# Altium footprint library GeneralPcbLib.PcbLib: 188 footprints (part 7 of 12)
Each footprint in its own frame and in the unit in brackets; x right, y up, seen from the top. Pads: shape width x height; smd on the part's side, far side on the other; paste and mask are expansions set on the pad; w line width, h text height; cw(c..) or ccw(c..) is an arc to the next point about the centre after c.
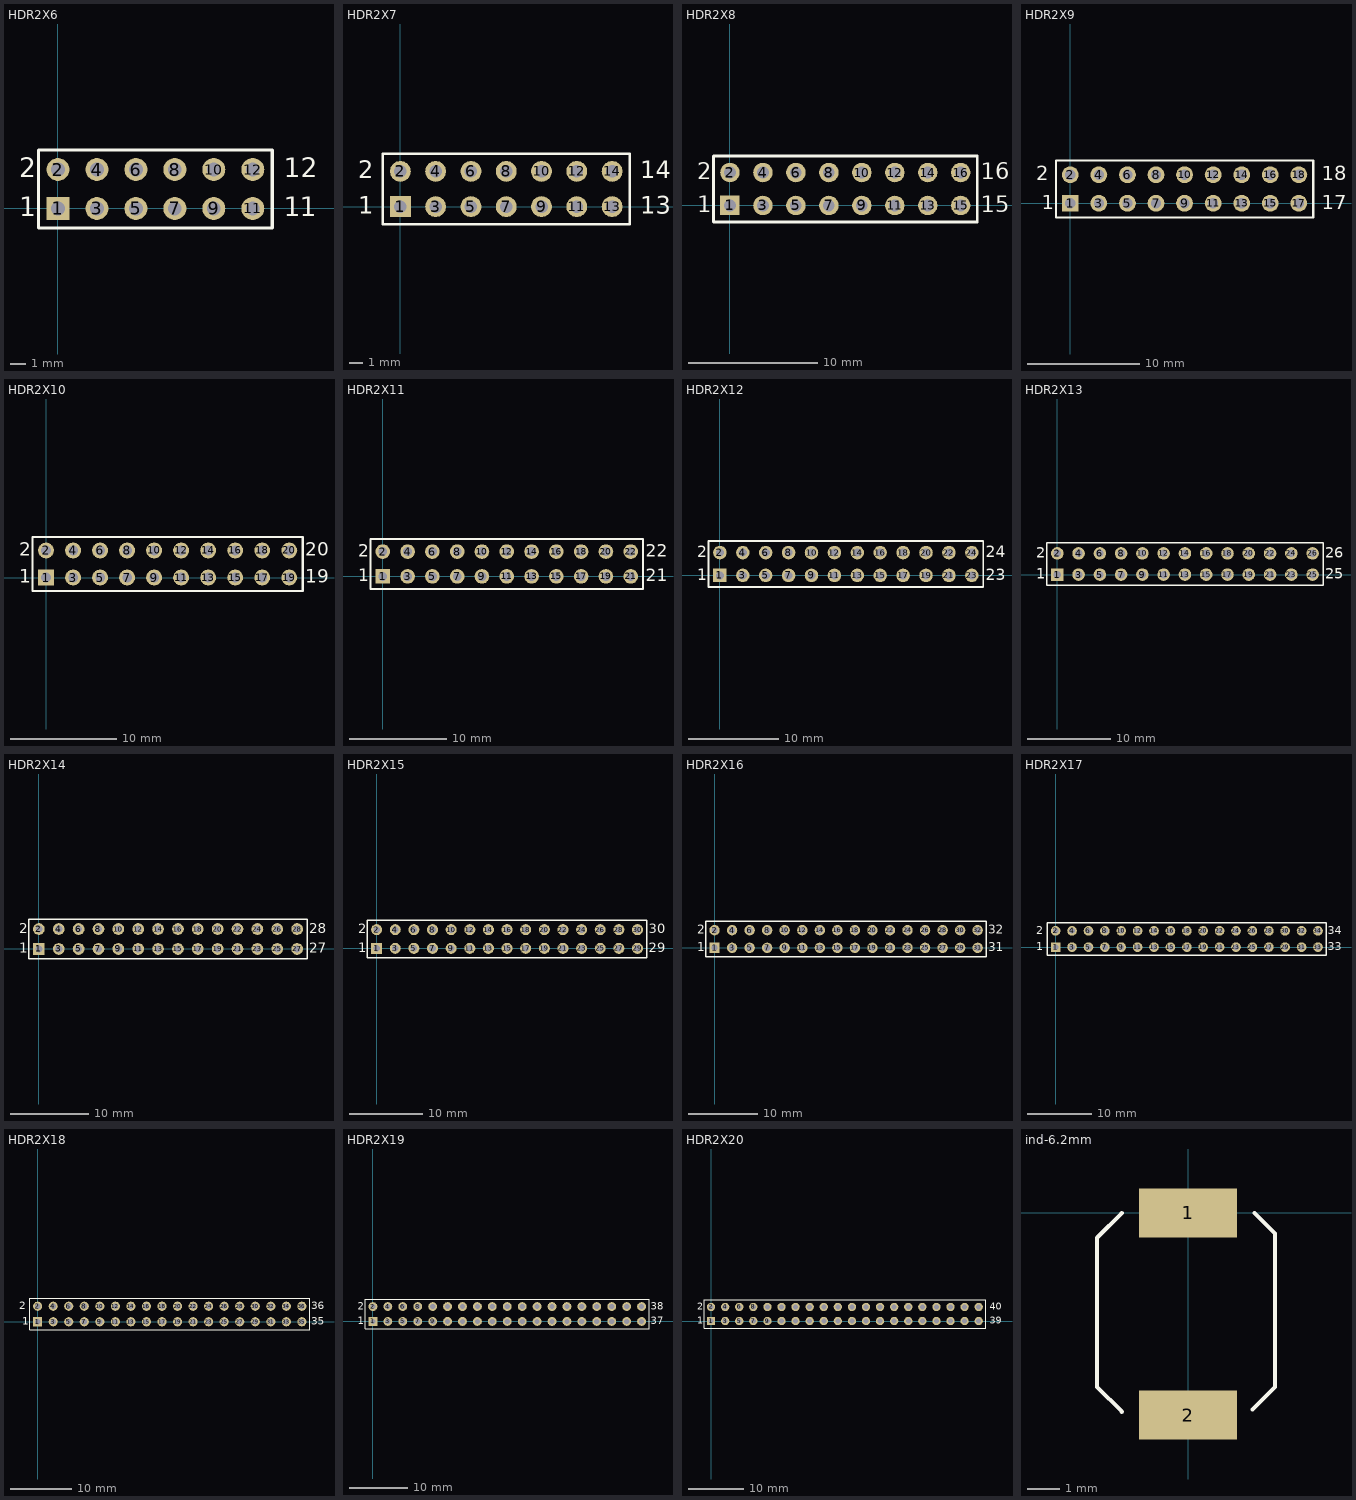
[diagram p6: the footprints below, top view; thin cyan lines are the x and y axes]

## HDR2X6 [mm] "Connector; Header; 6x2 Position"
pads (12):
  rect 1.5x1.5 hole 0.9: 1(0,0)
  round 1.5 hole 0.9: 2(0,2.54) 3(2.54,0) 4(2.54,2.54) 5(5.08,0) 6(5.08,2.54) 7(7.62,0) 8(7.62,2.54) 9(10.16,0) 10(10.16,2.54) 11(12.7,0) 12(12.7,2.54)
Top Overlay:
  lines w0.2: -1.27,-1.27 13.97,-1.27 13.97,3.81 -1.27,3.81 -1.27,-1.27
  text "12" at 14.732,2.032 h1.27
  text "1" at 15.748,-0.508 h1.27
  text "1" at 14.732,-0.508 h1.27
  text "1" at -2.54,-0.508 h1.27
  text "2" at -2.54,2.032 h1.27
3D body: height 7.58, standoff -2.94, extent 11.43,1.27 13.97,3.81
3D body: height 7.58, standoff -2.94, extent 11.43,-1.27 13.97,1.27
3D body: height 7.58, standoff -2.94, extent 8.89,1.27 11.43,3.81
3D body: height 7.58, standoff -2.94, extent 8.89,-1.27 11.43,1.27
3D body: height 7.58, standoff -2.94, extent 6.35,1.27 8.89,3.81
3D body: height 7.58, standoff -2.94, extent 6.35,-1.27 8.89,1.27
3D body: height 7.58, standoff -2.94, extent 3.81,1.27 6.35,3.81
3D body: height 7.58, standoff -2.94, extent 3.81,-1.27 6.35,1.27
3D body: height 7.58, standoff -2.94, extent 1.27,1.27 3.81,3.81
3D body: height 7.58, standoff -2.94, extent 1.27,-1.27 3.81,1.27
3D body: height 7.58, standoff -2.94, extent -1.27,1.27 1.27,3.81
3D body: height 7.58, standoff -2.94, extent -1.27,-1.27 1.27,1.27

## HDR2X7 [mm] "Connector; Header; 7x2 Position"
pads (14):
  rect 1.5x1.5 hole 0.9: 1(0,0)
  round 1.5 hole 0.9: 2(0,2.54) 3(2.54,0) 4(2.54,2.54) 5(5.08,0) 6(5.08,2.54) 7(7.62,0) 8(7.62,2.54) 9(10.16,0) 10(10.16,2.54) 11(12.7,0) 12(12.7,2.54) 13(15.24,0) 14(15.24,2.54)
Top Overlay:
  lines w0.2: -1.27,-1.27 16.51,-1.27 16.51,3.81 -1.27,3.81 -1.27,-1.27
  text "13" at 17.272,-0.508 h1.27
  text "14" at 17.272,2.032 h1.27
  text "1" at -3.048,-0.508 h1.27
  text "2" at -3.048,2.032 h1.27
3D body: height 7.58, standoff -2.94, extent 13.97,1.27 16.51,3.81
3D body: height 7.58, standoff -2.94, extent 13.97,-1.27 16.51,1.27
3D body: height 7.58, standoff -2.94, extent 11.43,1.27 13.97,3.81
3D body: height 7.58, standoff -2.94, extent 11.43,-1.27 13.97,1.27
3D body: height 7.58, standoff -2.94, extent 8.89,1.27 11.43,3.81
3D body: height 7.58, standoff -2.94, extent 8.89,-1.27 11.43,1.27
3D body: height 7.58, standoff -2.94, extent 6.35,1.27 8.89,3.81
3D body: height 7.58, standoff -2.94, extent 6.35,-1.27 8.89,1.27
3D body: height 7.58, standoff -2.94, extent 3.81,1.27 6.35,3.81
3D body: height 7.58, standoff -2.94, extent 3.81,-1.27 6.35,1.27
3D body: height 7.58, standoff -2.94, extent 1.27,1.27 3.81,3.81
3D body: height 7.58, standoff -2.94, extent 1.27,-1.27 3.81,1.27
3D body: height 7.58, standoff -2.94, extent -1.27,1.27 1.27,3.81
3D body: height 7.58, standoff -2.94, extent -1.27,-1.27 1.27,1.27

## HDR2X8 [mm] "Connector; Header; 8x2 Position"
pads (16):
  rect 1.5x1.5 hole 0.9: 1(0,0)
  round 1.5 hole 0.9: 2(0,2.54) 3(2.54,0) 4(2.54,2.54) 5(5.08,0) 6(5.08,2.54) 7(7.62,0) 8(7.62,2.54) 9(10.16,0) 10(10.16,2.54) 11(12.7,0) 12(12.7,2.54) 13(15.24,0) 14(15.24,2.54) 15(17.78,0) 16(17.78,2.54)
Top Overlay:
  lines w0.2: -1.27,-1.27 -1.27,3.81 19.05,3.81 19.05,-1.27 -1.27,-1.27
  text "2" at -2.54,2.032 h1.27
  text "1" at -2.54,-0.508 h1.27
  text "15" at 19.304,-0.508 h1.27
  text "16" at 19.304,2.032 h1.27
3D body: height 7.58, standoff -2.94, extent -1.27,-1.27 1.27,1.27
3D body: height 7.58, standoff -2.94, extent -1.27,1.27 1.27,3.81
3D body: height 7.58, standoff -2.94, extent 1.27,-1.27 3.81,1.27
3D body: height 7.58, standoff -2.94, extent 1.27,1.27 3.81,3.81
3D body: height 7.58, standoff -2.94, extent 3.81,-1.27 6.35,1.27
3D body: height 7.58, standoff -2.94, extent 3.81,1.27 6.35,3.81
3D body: height 7.58, standoff -2.94, extent 6.35,-1.27 8.89,1.27
3D body: height 7.58, standoff -2.94, extent 6.35,1.27 8.89,3.81
3D body: height 7.58, standoff -2.94, extent 8.89,-1.27 11.43,1.27
3D body: height 7.58, standoff -2.94, extent 8.89,1.27 11.43,3.81
3D body: height 7.58, standoff -2.94, extent 11.43,-1.27 13.97,1.27
3D body: height 7.58, standoff -2.94, extent 11.43,1.27 13.97,3.81
3D body: height 7.58, standoff -2.94, extent 13.97,-1.27 16.51,1.27
3D body: height 7.58, standoff -2.94, extent 13.97,1.27 16.51,3.81
3D body: height 7.58, standoff -2.94, extent 16.51,-1.27 19.05,1.27
3D body: height 7.58, standoff -2.94, extent 16.51,1.27 19.05,3.81

## HDR2X9 [mm] "Connector; Header; 9x2 Position"
pads (18):
  rect 1.5x1.5 hole 0.9: 1(0,0)
  round 1.5 hole 0.9: 2(0,2.54) 3(2.54,0) 4(2.54,2.54) 5(5.08,0) 6(5.08,2.54) 7(7.62,0) 8(7.62,2.54) 9(10.16,0) 10(10.16,2.54) 11(12.7,0) 12(12.7,2.54) 13(15.24,0) 14(15.24,2.54) 15(17.78,0) 16(17.78,2.54) 17(20.32,0) 18(20.32,2.54)
Top Overlay:
  lines w0.2: -1.27,-1.27 21.59,-1.27 21.59,3.81 -1.27,3.81 -1.27,-1.27
  text "18" at 22.352,2.032 h1.27
  text "17" at 22.352,-0.508 h1.27
  text "1" at -2.54,-0.508 h1.27
  text "2" at -3.048,2.032 h1.27
3D body: height 7.58, standoff -2.94, extent -1.27,1.27 1.27,3.81
3D body: height 7.58, standoff -2.94, extent -1.27,-1.27 1.27,1.27
3D body: height 7.58, standoff -2.94, extent 1.27,1.27 3.81,3.81
3D body: height 7.58, standoff -2.94, extent 1.27,-1.27 3.81,1.27
3D body: height 7.58, standoff -2.94, extent 3.81,1.27 6.35,3.81
3D body: height 7.58, standoff -2.94, extent 3.81,-1.27 6.35,1.27
3D body: height 7.58, standoff -2.94, extent 6.35,1.27 8.89,3.81
3D body: height 7.58, standoff -2.94, extent 6.35,-1.27 8.89,1.27
3D body: height 7.58, standoff -2.94, extent 8.89,1.27 11.43,3.81
3D body: height 7.58, standoff -2.94, extent 8.89,-1.27 11.43,1.27
3D body: height 7.58, standoff -2.94, extent 11.43,1.27 13.97,3.81
3D body: height 7.58, standoff -2.94, extent 11.43,-1.27 13.97,1.27
3D body: height 7.58, standoff -2.94, extent 13.97,1.27 16.51,3.81
3D body: height 7.58, standoff -2.94, extent 13.97,-1.27 16.51,1.27
3D body: height 7.58, standoff -2.94, extent 16.51,1.27 19.05,3.81
3D body: height 7.58, standoff -2.94, extent 16.51,-1.27 19.05,1.27
3D body: height 7.58, standoff -2.94, extent 19.05,1.27 21.59,3.81
3D body: height 7.58, standoff -2.94, extent 19.05,-1.27 21.59,1.27

## HDR2X10 [mm] "Connector; Header; 10x2 Position"
pads (20):
  rect 1.5x1.5 hole 0.9: 1(0,0)
  round 1.5 hole 0.9: 2(0,2.54) 3(2.54,0) 4(2.54,2.54) 5(5.08,0) 6(5.08,2.54) 7(7.62,0) 8(7.62,2.54) 9(10.16,0) 10(10.16,2.54) 11(12.7,0) 12(12.7,2.54) 13(15.24,0) 14(15.24,2.54) 15(17.78,0) 16(17.78,2.54) 17(20.32,0) 18(20.32,2.54) 19(22.86,0) 20(22.86,2.54)
Top Overlay:
  lines w0.2: -1.27,-1.27 -1.27,3.81 0.635,3.81 24.13,3.81 24.13,-1.27 0.635,-1.27 -1.27,-1.27
  text "2" at -2.54,2.032 h1.27
  text "1" at -2.54,-0.508 h1.27
  text "19" at 24.384,-0.508 h1.27
  text "20" at 24.384,2.032 h1.27
3D body: height 7.58, standoff -2.94, extent 21.59,1.27 24.13,3.81
3D body: height 7.58, standoff -2.94, extent 21.59,-1.27 24.13,1.27
3D body: height 7.58, standoff -2.94, extent 19.05,1.27 21.59,3.81
3D body: height 7.58, standoff -2.94, extent 19.05,-1.27 21.59,1.27
3D body: height 7.58, standoff -2.94, extent 16.51,1.27 19.05,3.81
3D body: height 7.58, standoff -2.94, extent 16.51,-1.27 19.05,1.27
3D body: height 7.58, standoff -2.94, extent 13.97,1.27 16.51,3.81
3D body: height 7.58, standoff -2.94, extent 13.97,-1.27 16.51,1.27
3D body: height 7.58, standoff -2.94, extent 11.43,1.27 13.97,3.81
3D body: height 7.58, standoff -2.94, extent 11.43,-1.27 13.97,1.27
3D body: height 7.58, standoff -2.94, extent 8.89,1.27 11.43,3.81
3D body: height 7.58, standoff -2.94, extent 8.89,-1.27 11.43,1.27
3D body: height 7.58, standoff -2.94, extent 6.35,1.27 8.89,3.81
3D body: height 7.58, standoff -2.94, extent 6.35,-1.27 8.89,1.27
3D body: height 7.58, standoff -2.94, extent 3.81,1.27 6.35,3.81
3D body: height 7.58, standoff -2.94, extent 3.81,-1.27 6.35,1.27
3D body: height 7.58, standoff -2.94, extent 1.27,1.27 3.81,3.81
3D body: height 7.58, standoff -2.94, extent 1.27,-1.27 3.81,1.27
3D body: height 7.58, standoff -2.94, extent -1.27,1.27 1.27,3.81
3D body: height 7.58, standoff -2.94, extent -1.27,-1.27 1.27,1.27

## HDR2X11 [mm] "Connector; Header; 11x2 Position"
pads (22):
  rect 1.5x1.5 hole 0.9: 1(0,0)
  round 1.5 hole 0.9: 2(0,2.54) 3(2.54,0) 4(2.54,2.54) 5(5.08,0) 6(5.08,2.54) 7(7.62,0) 8(7.62,2.54) 9(10.16,0) 10(10.16,2.54) 11(12.7,0) 12(12.7,2.54) 13(15.24,0) 14(15.24,2.54) 15(17.78,0) 16(17.78,2.54) 17(20.32,0) 18(20.32,2.54) 19(22.86,0) 20(22.86,2.54) 21(25.4,0) 22(25.4,2.54)
Top Overlay:
  lines w0.2: -1.27,-1.27 -1.27,3.81 26.67,3.81 26.67,-1.27 -1.27,-1.27
  text "1" at -2.54,-0.508 h1.27
  text "2" at -2.54,2.032 h1.27
  text "21" at 26.924,-0.508 h1.27
  text "22" at 26.924,2.032 h1.27
3D body: height 7.58, standoff -2.94, extent 24.13,1.27 26.67,3.81
3D body: height 7.58, standoff -2.94, extent 24.13,-1.27 26.67,1.27
3D body: height 7.58, standoff -2.94, extent 21.59,1.27 24.13,3.81
3D body: height 7.58, standoff -2.94, extent 21.59,-1.27 24.13,1.27
3D body: height 7.58, standoff -2.94, extent 19.05,1.27 21.59,3.81
3D body: height 7.58, standoff -2.94, extent 19.05,-1.27 21.59,1.27
3D body: height 7.58, standoff -2.94, extent 16.51,1.27 19.05,3.81
3D body: height 7.58, standoff -2.94, extent 16.51,-1.27 19.05,1.27
3D body: height 7.58, standoff -2.94, extent 13.97,1.27 16.51,3.81
3D body: height 7.58, standoff -2.94, extent 13.97,-1.27 16.51,1.27
3D body: height 7.58, standoff -2.94, extent 11.43,1.27 13.97,3.81
3D body: height 7.58, standoff -2.94, extent 11.43,-1.27 13.97,1.27
3D body: height 7.58, standoff -2.94, extent 8.89,1.27 11.43,3.81
3D body: height 7.58, standoff -2.94, extent 8.89,-1.27 11.43,1.27
3D body: height 7.58, standoff -2.94, extent 6.35,1.27 8.89,3.81
3D body: height 7.58, standoff -2.94, extent 6.35,-1.27 8.89,1.27
3D body: height 7.58, standoff -2.94, extent 3.81,1.27 6.35,3.81
3D body: height 7.58, standoff -2.94, extent 3.81,-1.27 6.35,1.27
3D body: height 7.58, standoff -2.94, extent 1.27,1.27 3.81,3.81
3D body: height 7.58, standoff -2.94, extent 1.27,-1.27 3.81,1.27
3D body: height 7.58, standoff -2.94, extent -1.27,1.27 1.27,3.81
3D body: height 7.58, standoff -2.94, extent -1.27,-1.27 1.27,1.27

## HDR2X12 [mm] "Connector; Header; 12x2 Position"
pads (24):
  rect 1.5x1.5 hole 0.9: 1(0,0)
  round 1.5 hole 0.9: 2(0,2.54) 3(2.54,0) 4(2.54,2.54) 5(5.08,0) 6(5.08,2.54) 7(7.62,0) 8(7.62,2.54) 9(10.16,0) 10(10.16,2.54) 11(12.7,0) 12(12.7,2.54) 13(15.24,0) 14(15.24,2.54) 15(17.78,0) 16(17.78,2.54) 17(20.32,0) 18(20.32,2.54) 19(22.86,0) 20(22.86,2.54) 21(25.4,0) 22(25.4,2.54) 23(27.94,0) 24(27.94,2.54)
Top Overlay:
  lines w0.2: -1.27,-1.27 -1.27,3.81 29.21,3.81 29.21,-1.27 -1.27,-1.27
  text "1" at -2.54,-0.508 h1.27
  text "2" at -2.54,2.032 h1.27
  text "23" at 29.464,-0.508 h1.27
  text "24" at 29.464,2.032 h1.27
3D body: height 7.58, standoff -2.94, extent 26.67,1.27 29.21,3.81
3D body: height 7.58, standoff -2.94, extent 26.67,-1.27 29.21,1.27
3D body: height 7.58, standoff -2.94, extent 24.13,1.27 26.67,3.81
3D body: height 7.58, standoff -2.94, extent 24.13,-1.27 26.67,1.27
3D body: height 7.58, standoff -2.94, extent 21.59,1.27 24.13,3.81
3D body: height 7.58, standoff -2.94, extent 21.59,-1.27 24.13,1.27
3D body: height 7.58, standoff -2.94, extent 19.05,1.27 21.59,3.81
3D body: height 7.58, standoff -2.94, extent 19.05,-1.27 21.59,1.27
3D body: height 7.58, standoff -2.94, extent 16.51,1.27 19.05,3.81
3D body: height 7.58, standoff -2.94, extent 16.51,-1.27 19.05,1.27
3D body: height 7.58, standoff -2.94, extent 13.97,1.27 16.51,3.81
3D body: height 7.58, standoff -2.94, extent 13.97,-1.27 16.51,1.27
3D body: height 7.58, standoff -2.94, extent 11.43,1.27 13.97,3.81
3D body: height 7.58, standoff -2.94, extent 11.43,-1.27 13.97,1.27
3D body: height 7.58, standoff -2.94, extent 8.89,1.27 11.43,3.81
3D body: height 7.58, standoff -2.94, extent 8.89,-1.27 11.43,1.27
3D body: height 7.58, standoff -2.94, extent 6.35,1.27 8.89,3.81
3D body: height 7.58, standoff -2.94, extent 6.35,-1.27 8.89,1.27
3D body: height 7.58, standoff -2.94, extent 3.81,1.27 6.35,3.81
3D body: height 7.58, standoff -2.94, extent 3.81,-1.27 6.35,1.27
3D body: height 7.58, standoff -2.94, extent 1.27,1.27 3.81,3.81
3D body: height 7.58, standoff -2.94, extent 1.27,-1.27 3.81,1.27
3D body: height 7.58, standoff -2.94, extent -1.27,1.27 1.27,3.81
3D body: height 7.58, standoff -2.94, extent -1.27,-1.27 1.27,1.27

## HDR2X13 [mm] "Connector; Header; 13x2 Position"
pads (26):
  rect 1.5x1.5 hole 0.9: 1(0,0)
  round 1.5 hole 0.9: 2(0,2.54) 3(2.54,0) 4(2.54,2.54) 5(5.08,0) 6(5.08,2.54) 7(7.62,0) 8(7.62,2.54) 9(10.16,0) 10(10.16,2.54) 11(12.7,0) 12(12.7,2.54) 13(15.24,0) 14(15.24,2.54) 15(17.78,0) 16(17.78,2.54) 17(20.32,0) 18(20.32,2.54) 19(22.86,0) 20(22.86,2.54) 21(25.4,0) 22(25.4,2.54) 23(27.94,0) 24(27.94,2.54) 25(30.48,0) 26(30.48,2.54)
Top Overlay:
  lines w0.2: -1.27,-1.27 -1.27,3.81 31.75,3.81 31.75,-1.27 -1.27,-1.27
  text "2" at -2.54,2.032 h1.27
  text "1" at -2.54,-0.508 h1.27
  text "25" at 32.004,-0.508 h1.27
  text "26" at 32.004,2.032 h1.27
3D body: height 7.58, standoff -2.94, extent -1.27,1.27 1.27,3.81
3D body: height 7.58, standoff -2.94, extent -1.27,-1.27 1.27,1.27
3D body: height 7.58, standoff -2.94, extent 1.27,1.27 3.81,3.81
3D body: height 7.58, standoff -2.94, extent 1.27,-1.27 3.81,1.27
3D body: height 7.58, standoff -2.94, extent 3.81,1.27 6.35,3.81
3D body: height 7.58, standoff -2.94, extent 3.81,-1.27 6.35,1.27
3D body: height 7.58, standoff -2.94, extent 6.35,1.27 8.89,3.81
3D body: height 7.58, standoff -2.94, extent 6.35,-1.27 8.89,1.27
3D body: height 7.58, standoff -2.94, extent 8.89,1.27 11.43,3.81
3D body: height 7.58, standoff -2.94, extent 8.89,-1.27 11.43,1.27
3D body: height 7.58, standoff -2.94, extent 11.43,1.27 13.97,3.81
3D body: height 7.58, standoff -2.94, extent 11.43,-1.27 13.97,1.27
3D body: height 7.58, standoff -2.94, extent 13.97,1.27 16.51,3.81
3D body: height 7.58, standoff -2.94, extent 13.97,-1.27 16.51,1.27
3D body: height 7.58, standoff -2.94, extent 16.51,1.27 19.05,3.81
3D body: height 7.58, standoff -2.94, extent 16.51,-1.27 19.05,1.27
3D body: height 7.58, standoff -2.94, extent 19.05,1.27 21.59,3.81
3D body: height 7.58, standoff -2.94, extent 19.05,-1.27 21.59,1.27
3D body: height 7.58, standoff -2.94, extent 21.59,1.27 24.13,3.81
3D body: height 7.58, standoff -2.94, extent 21.59,-1.27 24.13,1.27
3D body: height 7.58, standoff -2.94, extent 24.13,1.27 26.67,3.81
3D body: height 7.58, standoff -2.94, extent 24.13,-1.27 26.67,1.27
3D body: height 7.58, standoff -2.94, extent 26.67,1.27 29.21,3.81
3D body: height 7.58, standoff -2.94, extent 26.67,-1.27 29.21,1.27
3D body: height 7.58, standoff -2.94, extent 29.21,1.27 31.75,3.81
3D body: height 7.58, standoff -2.94, extent 29.21,-1.27 31.75,1.27

## HDR2X14 [mm] "Connector; Header; 14x2 Position"
pads (28):
  rect 1.5x1.5 hole 0.9: 1(0,0)
  round 1.5 hole 0.9: 2(0,2.54) 3(2.54,0) 4(2.54,2.54) 5(5.08,0) 6(5.08,2.54) 7(7.62,0) 8(7.62,2.54) 9(10.16,0) 10(10.16,2.54) 11(12.7,0) 12(12.7,2.54) 13(15.24,0) 14(15.24,2.54) 15(17.78,0) 16(17.78,2.54) 17(20.32,0) 18(20.32,2.54) 19(22.86,0) 20(22.86,2.54) 21(25.4,0) 22(25.4,2.54) 23(27.94,0) 24(27.94,2.54) 25(30.48,0) 26(30.48,2.54) 27(33.02,0) 28(33.02,2.54)
Top Overlay:
  lines w0.2: -1.27,-1.27 -1.27,3.81 34.29,3.81 34.29,-1.27 -1.27,-1.27
  text "2" at -2.54,2.032 h1.27
  text "1" at -2.54,-0.508 h1.27
  text "27" at 34.544,-0.508 h1.27
  text "28" at 34.544,2.032 h1.27
3D body: height 7.58, standoff -2.94, extent 31.75,1.27 34.29,3.81
3D body: height 7.58, standoff -2.94, extent 29.21,1.27 31.75,3.81
3D body: height 7.58, standoff -2.94, extent 31.75,-1.27 34.29,1.27
3D body: height 7.58, standoff -2.94, extent 29.21,-1.27 31.75,1.27
3D body: height 7.58, standoff -2.94, extent 26.67,1.27 29.21,3.81
3D body: height 7.58, standoff -2.94, extent 24.13,1.27 26.67,3.81
3D body: height 7.58, standoff -2.94, extent 21.59,1.27 24.13,3.81
3D body: height 7.58, standoff -2.94, extent 19.05,1.27 21.59,3.81
3D body: height 7.58, standoff -2.94, extent 26.67,-1.27 29.21,1.27
3D body: height 7.58, standoff -2.94, extent 24.13,-1.27 26.67,1.27
3D body: height 7.58, standoff -2.94, extent 21.59,-1.27 24.13,1.27
3D body: height 7.58, standoff -2.94, extent 19.05,-1.27 21.59,1.27
3D body: height 7.58, standoff -2.94, extent 16.51,1.27 19.05,3.81
3D body: height 7.58, standoff -2.94, extent 13.97,1.27 16.51,3.81
3D body: height 7.58, standoff -2.94, extent 11.43,1.27 13.97,3.81
3D body: height 7.58, standoff -2.94, extent 8.89,1.27 11.43,3.81
3D body: height 7.58, standoff -2.94, extent 16.51,-1.27 19.05,1.27
3D body: height 7.58, standoff -2.94, extent 13.97,-1.27 16.51,1.27
3D body: height 7.58, standoff -2.94, extent 11.43,-1.27 13.97,1.27
3D body: height 7.58, standoff -2.94, extent 8.89,-1.27 11.43,1.27
3D body: height 7.58, standoff -2.94, extent 6.35,1.27 8.89,3.81
3D body: height 7.58, standoff -2.94, extent 3.81,1.27 6.35,3.81
3D body: height 7.58, standoff -2.94, extent 1.27,1.27 3.81,3.81
3D body: height 7.58, standoff -2.94, extent -1.27,1.27 1.27,3.81
3D body: height 7.58, standoff -2.94, extent 6.35,-1.27 8.89,1.27
3D body: height 7.58, standoff -2.94, extent 3.81,-1.27 6.35,1.27
3D body: height 7.58, standoff -2.94, extent 1.27,-1.27 3.81,1.27
3D body: height 7.58, standoff -2.94, extent -1.27,-1.27 1.27,1.27

## HDR2X15 [mm] "Connector; Header; 15x2 Position"
pads (30):
  rect 1.5x1.5 hole 0.9: 1(0,0)
  round 1.5 hole 0.9: 2(0,2.54) 3(2.54,0) 4(2.54,2.54) 5(5.08,0) 6(5.08,2.54) 7(7.62,0) 8(7.62,2.54) 9(10.16,0) 10(10.16,2.54) 11(12.7,0) 12(12.7,2.54) 13(15.24,0) 14(15.24,2.54) 15(17.78,0) 16(17.78,2.54) 17(20.32,0) 18(20.32,2.54) 19(22.86,0) 20(22.86,2.54) 21(25.4,0) 22(25.4,2.54) 23(27.94,0) 24(27.94,2.54) 25(30.48,0) 26(30.48,2.54) 27(33.02,0) 28(33.02,2.54) 29(35.56,0) 30(35.56,2.54)
Top Overlay:
  lines w0.2: -1.27,-1.27 -1.27,3.81 36.83,3.81 36.83,-1.27 -1.27,-1.27
  text "30" at 37.084,2.032 h1.27
  text "29" at 37.084,-0.508 h1.27
  text "2" at -2.54,2.032 h1.27
  text "1" at -2.54,-0.508 h1.27
3D body: height 7.58, standoff -2.94, extent -1.27,-1.27 1.27,1.27
3D body: height 7.58, standoff -2.94, extent 1.27,-1.27 3.81,1.27
3D body: height 7.58, standoff -2.94, extent 3.81,-1.27 6.35,1.27
3D body: height 7.58, standoff -2.94, extent 6.35,-1.27 8.89,1.27
3D body: height 7.58, standoff -2.94, extent -1.27,1.27 1.27,3.81
3D body: height 7.58, standoff -2.94, extent 1.27,1.27 3.81,3.81
3D body: height 7.58, standoff -2.94, extent 3.81,1.27 6.35,3.81
3D body: height 7.58, standoff -2.94, extent 6.35,1.27 8.89,3.81
3D body: height 7.58, standoff -2.94, extent 8.89,-1.27 11.43,1.27
3D body: height 7.58, standoff -2.94, extent 11.43,-1.27 13.97,1.27
3D body: height 7.58, standoff -2.94, extent 13.97,-1.27 16.51,1.27
3D body: height 7.58, standoff -2.94, extent 16.51,-1.27 19.05,1.27
3D body: height 7.58, standoff -2.94, extent 8.89,1.27 11.43,3.81
3D body: height 7.58, standoff -2.94, extent 11.43,1.27 13.97,3.81
3D body: height 7.58, standoff -2.94, extent 13.97,1.27 16.51,3.81
3D body: height 7.58, standoff -2.94, extent 16.51,1.27 19.05,3.81
3D body: height 7.58, standoff -2.94, extent 19.05,-1.27 21.59,1.27
3D body: height 7.58, standoff -2.94, extent 21.59,-1.27 24.13,1.27
3D body: height 7.58, standoff -2.94, extent 24.13,-1.27 26.67,1.27
3D body: height 7.58, standoff -2.94, extent 26.67,-1.27 29.21,1.27
3D body: height 7.58, standoff -2.94, extent 19.05,1.27 21.59,3.81
3D body: height 7.58, standoff -2.94, extent 21.59,1.27 24.13,3.81
3D body: height 7.58, standoff -2.94, extent 24.13,1.27 26.67,3.81
3D body: height 7.58, standoff -2.94, extent 26.67,1.27 29.21,3.81
3D body: height 7.58, standoff -2.94, extent 29.21,-1.27 31.75,1.27
3D body: height 7.58, standoff -2.94, extent 31.75,-1.27 34.29,1.27
3D body: height 7.58, standoff -2.94, extent 34.29,-1.27 36.83,1.27
3D body: height 7.58, standoff -2.94, extent 29.21,1.27 31.75,3.81
3D body: height 7.58, standoff -2.94, extent 31.75,1.27 34.29,3.81
3D body: height 7.58, standoff -2.94, extent 34.29,1.27 36.83,3.81

## HDR2X16 [mm] "Connector; Header; 16x2 Position"
pads (32):
  rect 1.5x1.5 hole 0.9: 1(0,0)
  round 1.5 hole 0.9: 2(0,2.54) 3(2.54,0) 4(2.54,2.54) 5(5.08,0) 6(5.08,2.54) 7(7.62,0) 8(7.62,2.54) 9(10.16,0) 10(10.16,2.54) 11(12.7,0) 12(12.7,2.54) 13(15.24,0) 14(15.24,2.54) 15(17.78,0) 16(17.78,2.54) 17(20.32,0) 18(20.32,2.54) 19(22.86,0) 20(22.86,2.54) 21(25.4,0) 22(25.4,2.54) 23(27.94,0) 24(27.94,2.54) 25(30.48,0) 26(30.48,2.54) 27(33.02,0) 28(33.02,2.54) 29(35.56,0) 30(35.56,2.54) 31(38.1,0) 32(38.1,2.54)
Top Overlay:
  lines w0.2: -1.27,-1.27 -1.27,3.81 39.37,3.81 39.37,-1.27 -1.27,-1.27
  text "32" at 39.624,2.032 h1.27
  text "31" at 39.624,-0.508 h1.27
  text "1" at -2.54,-0.508 h1.27
  text "2" at -2.54,2.032 h1.27
3D body: height 7.58, standoff -2.94, extent 36.83,1.27 39.37,3.81
3D body: height 7.58, standoff -2.94, extent 34.29,1.27 36.83,3.81
3D body: height 7.58, standoff -2.94, extent 31.75,1.27 34.29,3.81
3D body: height 7.58, standoff -2.94, extent 29.21,1.27 31.75,3.81
3D body: height 7.58, standoff -2.94, extent 36.83,-1.27 39.37,1.27
3D body: height 7.58, standoff -2.94, extent 34.29,-1.27 36.83,1.27
3D body: height 7.58, standoff -2.94, extent 31.75,-1.27 34.29,1.27
3D body: height 7.58, standoff -2.94, extent 29.21,-1.27 31.75,1.27
3D body: height 7.58, standoff -2.94, extent 26.67,1.27 29.21,3.81
3D body: height 7.58, standoff -2.94, extent 24.13,1.27 26.67,3.81
3D body: height 7.58, standoff -2.94, extent 21.59,1.27 24.13,3.81
3D body: height 7.58, standoff -2.94, extent 19.05,1.27 21.59,3.81
3D body: height 7.58, standoff -2.94, extent 26.67,-1.27 29.21,1.27
3D body: height 7.58, standoff -2.94, extent 24.13,-1.27 26.67,1.27
3D body: height 7.58, standoff -2.94, extent 21.59,-1.27 24.13,1.27
3D body: height 7.58, standoff -2.94, extent 19.05,-1.27 21.59,1.27
3D body: height 7.58, standoff -2.94, extent 16.51,1.27 19.05,3.81
3D body: height 7.58, standoff -2.94, extent 13.97,1.27 16.51,3.81
3D body: height 7.58, standoff -2.94, extent 11.43,1.27 13.97,3.81
3D body: height 7.58, standoff -2.94, extent 8.89,1.27 11.43,3.81
3D body: height 7.58, standoff -2.94, extent 16.51,-1.27 19.05,1.27
3D body: height 7.58, standoff -2.94, extent 13.97,-1.27 16.51,1.27
3D body: height 7.58, standoff -2.94, extent 11.43,-1.27 13.97,1.27
3D body: height 7.58, standoff -2.94, extent 8.89,-1.27 11.43,1.27
3D body: height 7.58, standoff -2.94, extent 6.35,1.27 8.89,3.81
3D body: height 7.58, standoff -2.94, extent 3.81,1.27 6.35,3.81
3D body: height 7.58, standoff -2.94, extent 1.27,1.27 3.81,3.81
3D body: height 7.58, standoff -2.94, extent -1.27,1.27 1.27,3.81
3D body: height 7.58, standoff -2.94, extent 6.35,-1.27 8.89,1.27
3D body: height 7.58, standoff -2.94, extent 3.81,-1.27 6.35,1.27
3D body: height 7.58, standoff -2.94, extent 1.27,-1.27 3.81,1.27
3D body: height 7.58, standoff -2.94, extent -1.27,-1.27 1.27,1.27

## HDR2X17 [mm] "Connector; Header; 17x2 Position"
pads (34):
  rect 1.5x1.5 hole 0.9: 1(0,0)
  round 1.5 hole 0.9: 2(0,2.54) 3(2.54,0) 4(2.54,2.54) 5(5.08,0) 6(5.08,2.54) 7(7.62,0) 8(7.62,2.54) 9(10.16,0) 10(10.16,2.54) 11(12.7,0) 12(12.7,2.54) 13(15.24,0) 14(15.24,2.54) 15(17.78,0) 16(17.78,2.54) 17(20.32,0) 18(20.32,2.54) 19(22.86,0) 20(22.86,2.54) 21(25.4,0) 22(25.4,2.54) 23(27.94,0) 24(27.94,2.54) 25(30.48,0) 26(30.48,2.54) 27(33.02,0) 28(33.02,2.54) 29(35.56,0) 30(35.56,2.54) 31(38.1,0) 32(38.1,2.54) 33(40.64,0) 34(40.64,2.54)
Top Overlay:
  lines w0.2: -1.27,-1.27 41.91,-1.27 41.91,3.81 -1.27,3.81 -1.27,-1.27
  text "34" at 42.164,2.032 h1.27
  text "33" at 42.164,-0.508 h1.27
  text "1" at -3.048,-0.508 h1.27
  text "2" at -3.048,2.032 h1.27
3D body: height 7.58, standoff -2.94, extent -1.27,-1.27 1.27,1.27
3D body: height 7.58, standoff -2.94, extent 1.27,-1.27 3.81,1.27
3D body: height 7.58, standoff -2.94, extent 3.81,-1.27 6.35,1.27
3D body: height 7.58, standoff -2.94, extent 6.35,-1.27 8.89,1.27
3D body: height 7.58, standoff -2.94, extent -1.27,1.27 1.27,3.81
3D body: height 7.58, standoff -2.94, extent 1.27,1.27 3.81,3.81
3D body: height 7.58, standoff -2.94, extent 3.81,1.27 6.35,3.81
3D body: height 7.58, standoff -2.94, extent 6.35,1.27 8.89,3.81
3D body: height 7.58, standoff -2.94, extent 8.89,-1.27 11.43,1.27
3D body: height 7.58, standoff -2.94, extent 11.43,-1.27 13.97,1.27
3D body: height 7.58, standoff -2.94, extent 13.97,-1.27 16.51,1.27
3D body: height 7.58, standoff -2.94, extent 16.51,-1.27 19.05,1.27
3D body: height 7.58, standoff -2.94, extent 8.89,1.27 11.43,3.81
3D body: height 7.58, standoff -2.94, extent 11.43,1.27 13.97,3.81
3D body: height 7.58, standoff -2.94, extent 13.97,1.27 16.51,3.81
3D body: height 7.58, standoff -2.94, extent 16.51,1.27 19.05,3.81
3D body: height 7.58, standoff -2.94, extent 19.05,-1.27 21.59,1.27
3D body: height 7.58, standoff -2.94, extent 21.59,-1.27 24.13,1.27
3D body: height 7.58, standoff -2.94, extent 24.13,-1.27 26.67,1.27
3D body: height 7.58, standoff -2.94, extent 26.67,-1.27 29.21,1.27
3D body: height 7.58, standoff -2.94, extent 19.05,1.27 21.59,3.81
3D body: height 7.58, standoff -2.94, extent 21.59,1.27 24.13,3.81
3D body: height 7.58, standoff -2.94, extent 24.13,1.27 26.67,3.81
3D body: height 7.58, standoff -2.94, extent 26.67,1.27 29.21,3.81
3D body: height 7.58, standoff -2.94, extent 29.21,-1.27 31.75,1.27
3D body: height 7.58, standoff -2.94, extent 31.75,-1.27 34.29,1.27
3D body: height 7.58, standoff -2.94, extent 34.29,-1.27 36.83,1.27
3D body: height 7.58, standoff -2.94, extent 36.83,-1.27 39.37,1.27
3D body: height 7.58, standoff -2.94, extent 29.21,1.27 31.75,3.81
3D body: height 7.58, standoff -2.94, extent 31.75,1.27 34.29,3.81
3D body: height 7.58, standoff -2.94, extent 34.29,1.27 36.83,3.81
3D body: height 7.58, standoff -2.94, extent 36.83,1.27 39.37,3.81
3D body: height 7.58, standoff -2.94, extent 39.37,-1.27 41.91,1.27
3D body: height 7.58, standoff -2.94, extent 39.37,1.27 41.91,3.81

## HDR2X18 [mm] "Connector; Header; 18x2 Position"
pads (36):
  rect 1.5x1.5 hole 0.9: 1(0,0)
  round 1.5 hole 0.9: 2(0,2.54) 3(2.54,0) 4(2.54,2.54) 5(5.08,0) 6(5.08,2.54) 7(7.62,0) 8(7.62,2.54) 9(10.16,0) 10(10.16,2.54) 11(12.7,0) 12(12.7,2.54) 13(15.24,0) 14(15.24,2.54) 15(17.78,0) 16(17.78,2.54) 17(20.32,0) 18(20.32,2.54) 19(22.86,0) 20(22.86,2.54) 21(25.4,0) 22(25.4,2.54) 23(27.94,0) 24(27.94,2.54) 25(30.48,0) 26(30.48,2.54) 27(33.02,0) 28(33.02,2.54) 29(35.56,0) 30(35.56,2.54) 31(38.1,0) 32(38.1,2.54) 33(40.64,0) 34(40.64,2.54) 35(43.18,0) 36(43.18,2.54)
Top Overlay:
  lines w0.2: -1.27,-1.27 44.45,-1.27 44.45,3.81 -1.27,3.81 -1.27,-1.27
  text "36" at 44.704,2.032 h1.27
  text "35" at 44.704,-0.508 h1.27
  text "1" at -2.54,-0.508 h1.27
  text "2" at -3.048,2.032 h1.27
3D body: height 7.58, standoff -2.94, extent 41.91,1.27 44.45,3.81
3D body: height 7.58, standoff -2.94, extent 39.37,1.27 41.91,3.81
3D body: height 7.58, standoff -2.94, extent 41.91,-1.27 44.45,1.27
3D body: height 7.58, standoff -2.94, extent 39.37,-1.27 41.91,1.27
3D body: height 7.58, standoff -2.94, extent 36.83,1.27 39.37,3.81
3D body: height 7.58, standoff -2.94, extent 34.29,1.27 36.83,3.81
3D body: height 7.58, standoff -2.94, extent 31.75,1.27 34.29,3.81
3D body: height 7.58, standoff -2.94, extent 29.21,1.27 31.75,3.81
3D body: height 7.58, standoff -2.94, extent 36.83,-1.27 39.37,1.27
3D body: height 7.58, standoff -2.94, extent 34.29,-1.27 36.83,1.27
3D body: height 7.58, standoff -2.94, extent 31.75,-1.27 34.29,1.27
3D body: height 7.58, standoff -2.94, extent 29.21,-1.27 31.75,1.27
3D body: height 7.58, standoff -2.94, extent 26.67,1.27 29.21,3.81
3D body: height 7.58, standoff -2.94, extent 24.13,1.27 26.67,3.81
3D body: height 7.58, standoff -2.94, extent 21.59,1.27 24.13,3.81
3D body: height 7.58, standoff -2.94, extent 19.05,1.27 21.59,3.81
3D body: height 7.58, standoff -2.94, extent 26.67,-1.27 29.21,1.27
3D body: height 7.58, standoff -2.94, extent 24.13,-1.27 26.67,1.27
3D body: height 7.58, standoff -2.94, extent 21.59,-1.27 24.13,1.27
3D body: height 7.58, standoff -2.94, extent 19.05,-1.27 21.59,1.27
3D body: height 7.58, standoff -2.94, extent 16.51,1.27 19.05,3.81
3D body: height 7.58, standoff -2.94, extent 13.97,1.27 16.51,3.81
3D body: height 7.58, standoff -2.94, extent 11.43,1.27 13.97,3.81
3D body: height 7.58, standoff -2.94, extent 8.89,1.27 11.43,3.81
3D body: height 7.58, standoff -2.94, extent 16.51,-1.27 19.05,1.27
3D body: height 7.58, standoff -2.94, extent 13.97,-1.27 16.51,1.27
3D body: height 7.58, standoff -2.94, extent 11.43,-1.27 13.97,1.27
3D body: height 7.58, standoff -2.94, extent 8.89,-1.27 11.43,1.27
3D body: height 7.58, standoff -2.94, extent 6.35,1.27 8.89,3.81
3D body: height 7.58, standoff -2.94, extent 3.81,1.27 6.35,3.81
3D body: height 7.58, standoff -2.94, extent 1.27,1.27 3.81,3.81
3D body: height 7.58, standoff -2.94, extent -1.27,1.27 1.27,3.81
3D body: height 7.58, standoff -2.94, extent 6.35,-1.27 8.89,1.27
3D body: height 7.58, standoff -2.94, extent 3.81,-1.27 6.35,1.27
3D body: height 7.58, standoff -2.94, extent 1.27,-1.27 3.81,1.27
3D body: height 7.58, standoff -2.94, extent -1.27,-1.27 1.27,1.27

## HDR2X19 [mm] "Connector; Header; 19x2 Position"
pads (38):
  rect 1.5x1.5 hole 0.9: 1(0,0)
  round 1.5 hole 0.9: 2(0,2.54) 3(2.54,0) 4(2.54,2.54) 5(5.08,0) 6(5.08,2.54) 7(7.62,0) 8(7.62,2.54) 9(10.16,0) 10(10.16,2.54) 11(12.7,0) 12(12.7,2.54) 13(15.24,0) 14(15.24,2.54) 15(17.78,0) 16(17.78,2.54) 17(20.32,0) 18(20.32,2.54) 19(22.86,0) 20(22.86,2.54) 21(25.4,0) 22(25.4,2.54) 23(27.94,0) 24(27.94,2.54) 25(30.48,0) 26(30.48,2.54) 27(33.02,0) 28(33.02,2.54) 29(35.56,0) 30(35.56,2.54) 31(38.1,0) 32(38.1,2.54) 33(40.64,0) 34(40.64,2.54) 35(43.18,0) 36(43.18,2.54) 37(45.72,0) 38(45.72,2.54)
Top Overlay:
  lines w0.2: -1.27,-1.27 -1.27,3.81 46.99,3.81 46.99,-1.27 -1.27,-1.27
  text "38" at 47.244,2.032 h1.27
  text "37" at 47.244,-0.508 h1.27
  text "1" at -2.54,-0.508 h1.27
  text "2" at -2.54,2.032 h1.27
3D body: height 7.58, standoff -2.94, extent -1.27,-1.27 1.27,1.27
3D body: height 7.58, standoff -2.94, extent 1.27,-1.27 3.81,1.27
3D body: height 7.58, standoff -2.94, extent 3.81,-1.27 6.35,1.27
3D body: height 7.58, standoff -2.94, extent 6.35,-1.27 8.89,1.27
3D body: height 7.58, standoff -2.94, extent -1.27,1.27 1.27,3.81
3D body: height 7.58, standoff -2.94, extent 1.27,1.27 3.81,3.81
3D body: height 7.58, standoff -2.94, extent 3.81,1.27 6.35,3.81
3D body: height 7.58, standoff -2.94, extent 6.35,1.27 8.89,3.81
3D body: height 7.58, standoff -2.94, extent 8.89,-1.27 11.43,1.27
3D body: height 7.58, standoff -2.94, extent 11.43,-1.27 13.97,1.27
3D body: height 7.58, standoff -2.94, extent 13.97,-1.27 16.51,1.27
3D body: height 7.58, standoff -2.94, extent 16.51,-1.27 19.05,1.27
3D body: height 7.58, standoff -2.94, extent 8.89,1.27 11.43,3.81
3D body: height 7.58, standoff -2.94, extent 11.43,1.27 13.97,3.81
3D body: height 7.58, standoff -2.94, extent 13.97,1.27 16.51,3.81
3D body: height 7.58, standoff -2.94, extent 16.51,1.27 19.05,3.81
3D body: height 7.58, standoff -2.94, extent 19.05,-1.27 21.59,1.27
3D body: height 7.58, standoff -2.94, extent 21.59,-1.27 24.13,1.27
3D body: height 7.58, standoff -2.94, extent 24.13,-1.27 26.67,1.27
3D body: height 7.58, standoff -2.94, extent 26.67,-1.27 29.21,1.27
3D body: height 7.58, standoff -2.94, extent 19.05,1.27 21.59,3.81
3D body: height 7.58, standoff -2.94, extent 21.59,1.27 24.13,3.81
3D body: height 7.58, standoff -2.94, extent 24.13,1.27 26.67,3.81
3D body: height 7.58, standoff -2.94, extent 26.67,1.27 29.21,3.81
3D body: height 7.58, standoff -2.94, extent 29.21,-1.27 31.75,1.27
3D body: height 7.58, standoff -2.94, extent 31.75,-1.27 34.29,1.27
3D body: height 7.58, standoff -2.94, extent 34.29,-1.27 36.83,1.27
3D body: height 7.58, standoff -2.94, extent 36.83,-1.27 39.37,1.27
3D body: height 7.58, standoff -2.94, extent 29.21,1.27 31.75,3.81
3D body: height 7.58, standoff -2.94, extent 31.75,1.27 34.29,3.81
3D body: height 7.58, standoff -2.94, extent 34.29,1.27 36.83,3.81
3D body: height 7.58, standoff -2.94, extent 36.83,1.27 39.37,3.81
3D body: height 7.58, standoff -2.94, extent 39.37,-1.27 41.91,1.27
3D body: height 7.58, standoff -2.94, extent 41.91,-1.27 44.45,1.27
3D body: height 7.58, standoff -2.94, extent 44.45,-1.27 46.99,1.27
3D body: height 7.58, standoff -2.94, extent 39.37,1.27 41.91,3.81
3D body: height 7.58, standoff -2.94, extent 41.91,1.27 44.45,3.81
3D body: height 7.58, standoff -2.94, extent 44.45,1.27 46.99,3.81

## HDR2X20 [mm] "Connector; Header; 20x2 Position"
pads (40):
  rect 1.5x1.5 hole 0.9: 1(0,0)
  round 1.5 hole 0.9: 2(0,2.54) 3(2.54,0) 4(2.54,2.54) 5(5.08,0) 6(5.08,2.54) 7(7.62,0) 8(7.62,2.54) 9(10.16,0) 10(10.16,2.54) 11(12.7,0) 12(12.7,2.54) 13(15.24,0) 14(15.24,2.54) 15(17.78,0) 16(17.78,2.54) 17(20.32,0) 18(20.32,2.54) 19(22.86,0) 20(22.86,2.54) 21(25.4,0) 22(25.4,2.54) 23(27.94,0) 24(27.94,2.54) 25(30.48,0) 26(30.48,2.54) 27(33.02,0) 28(33.02,2.54) 29(35.56,0) 30(35.56,2.54) 31(38.1,0) 32(38.1,2.54) 33(40.64,0) 34(40.64,2.54) 35(43.18,0) 36(43.18,2.54) 37(45.72,0) 38(45.72,2.54) 39(48.26,0) 40(48.26,2.54)
Top Overlay:
  lines w0.2: -1.27,-1.27 49.53,-1.27 49.53,3.81 -1.27,3.81 -1.27,-1.27
  text "1" at -2.54,-0.508 h1.27
  text "2" at -2.54,2.032 h1.27
  text "40" at 50.292,2.032 h1.27
  text "39" at 50.292,-0.508 h1.27
3D body: height 7.58, standoff -2.94, extent 46.99,1.27 49.53,3.81
3D body: height 7.58, standoff -2.94, extent 44.45,1.27 46.99,3.81
3D body: height 7.58, standoff -2.94, extent 41.91,1.27 44.45,3.81
3D body: height 7.58, standoff -2.94, extent 39.37,1.27 41.91,3.81
3D body: height 7.58, standoff -2.94, extent 46.99,-1.27 49.53,1.27
3D body: height 7.58, standoff -2.94, extent 44.45,-1.27 46.99,1.27
3D body: height 7.58, standoff -2.94, extent 41.91,-1.27 44.45,1.27
3D body: height 7.58, standoff -2.94, extent 39.37,-1.27 41.91,1.27
3D body: height 7.58, standoff -2.94, extent 36.83,1.27 39.37,3.81
3D body: height 7.58, standoff -2.94, extent 34.29,1.27 36.83,3.81
3D body: height 7.58, standoff -2.94, extent 31.75,1.27 34.29,3.81
3D body: height 7.58, standoff -2.94, extent 29.21,1.27 31.75,3.81
3D body: height 7.58, standoff -2.94, extent 36.83,-1.27 39.37,1.27
3D body: height 7.58, standoff -2.94, extent 34.29,-1.27 36.83,1.27
3D body: height 7.58, standoff -2.94, extent 31.75,-1.27 34.29,1.27
3D body: height 7.58, standoff -2.94, extent 29.21,-1.27 31.75,1.27
3D body: height 7.58, standoff -2.94, extent 26.67,1.27 29.21,3.81
3D body: height 7.58, standoff -2.94, extent 24.13,1.27 26.67,3.81
3D body: height 7.58, standoff -2.94, extent 21.59,1.27 24.13,3.81
3D body: height 7.58, standoff -2.94, extent 19.05,1.27 21.59,3.81
3D body: height 7.58, standoff -2.94, extent 26.67,-1.27 29.21,1.27
3D body: height 7.58, standoff -2.94, extent 24.13,-1.27 26.67,1.27
3D body: height 7.58, standoff -2.94, extent 21.59,-1.27 24.13,1.27
3D body: height 7.58, standoff -2.94, extent 19.05,-1.27 21.59,1.27
3D body: height 7.58, standoff -2.94, extent 16.51,1.27 19.05,3.81
3D body: height 7.58, standoff -2.94, extent 13.97,1.27 16.51,3.81
3D body: height 7.58, standoff -2.94, extent 11.43,1.27 13.97,3.81
3D body: height 7.58, standoff -2.94, extent 8.89,1.27 11.43,3.81
3D body: height 7.58, standoff -2.94, extent 16.51,-1.27 19.05,1.27
3D body: height 7.58, standoff -2.94, extent 13.97,-1.27 16.51,1.27
3D body: height 7.58, standoff -2.94, extent 11.43,-1.27 13.97,1.27
3D body: height 7.58, standoff -2.94, extent 8.89,-1.27 11.43,1.27
3D body: height 7.58, standoff -2.94, extent -1.27,-1.27 1.27,1.27
3D body: height 7.58, standoff -2.94, extent 1.27,-1.27 3.81,1.27
3D body: height 7.58, standoff -2.94, extent 3.81,-1.27 6.35,1.27
3D body: height 7.58, standoff -2.94, extent 6.35,-1.27 8.89,1.27
3D body: height 7.58, standoff -2.94, extent -1.27,1.27 1.27,3.81
3D body: height 7.58, standoff -2.94, extent 1.27,1.27 3.81,3.81
3D body: height 7.58, standoff -2.94, extent 3.81,1.27 6.35,3.81
3D body: height 7.58, standoff -2.94, extent 6.35,1.27 8.89,3.81

## ind-6.2mm [mm]
pads (2):
  rect 3x1.5 smd: 1(0,0) 2(0,-6.2)
Top Overlay:
  lines w0.127: -2.032,-6.096 -2.794,-5.334 -2.794,-0.762 -2.032,0 ; 1.971,-6.03 2.667,-5.334 2.667,-0.635 2.032,0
